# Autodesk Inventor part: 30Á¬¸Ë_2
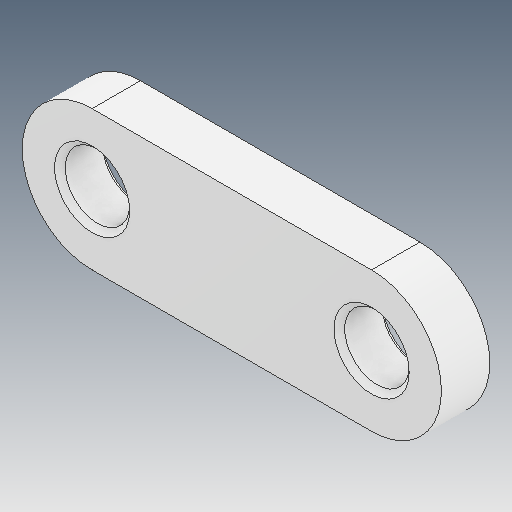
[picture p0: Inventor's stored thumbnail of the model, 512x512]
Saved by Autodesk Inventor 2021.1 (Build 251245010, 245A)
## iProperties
Created: 2021-05
Part Number: 30Á¬¸Ë_2
Material: Ogólny
Document SubType Name: Modeling
Designer: user
Density: 1 g/cm^3
Appearance: Domyślna
Author: user
Revision Number: ÈÎºÎ
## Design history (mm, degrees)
feature "ÊäÈë1"
node "Bryła1"
